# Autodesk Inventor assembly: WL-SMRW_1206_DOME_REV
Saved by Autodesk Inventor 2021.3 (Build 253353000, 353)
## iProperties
Created: 2023-03
Part Number: WL-SMRW_1206_DOME_REV
Document SubType Name: Assembly
Designer: AdminForWorker
Title: WL-SMRW_1206_DOME_REV
Author: AdminForWorker
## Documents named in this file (7)
- z:\worker\convert-fusion-r08-cosv3\tmp\job-1\3553\output\files\82b4d9ad-b575-4129-b9ca-4964d6b72adf\WL-SMRW_1206_DOME_REV.iam
- z:\worker\convert-fusion-r08-cosv3\tmp\job-1\3553\output\files\82b4d9ad-b575-4129-b9ca-4964d6b72adf\Base.ipt
- z:\worker\convert-fusion-r08-cosv3\tmp\job-1\3553\output\files\82b4d9ad-b575-4129-b9ca-4964d6b72adf\Contacts.ipt
- z:\worker\convert-fusion-r08-cosv3\tmp\job-1\3553\output\files\82b4d9ad-b575-4129-b9ca-4964d6b72adf\Contacts (1).ipt
- z:\worker\convert-fusion-r08-cosv3\tmp\job-1\3553\output\files\82b4d9ad-b575-4129-b9ca-4964d6b72adf\Cup.ipt
- z:\worker\convert-fusion-r08-cosv3\tmp\job-1\3553\output\files\82b4d9ad-b575-4129-b9ca-4964d6b72adf\Marking.ipt
- z:\worker\convert-fusion-r08-cosv3\tmp\job-1\3553\output\files\82b4d9ad-b575-4129-b9ca-4964d6b72adf\LED.ipt
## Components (6 placed, 6 different names)
1. Base:1
2. Contacts:1
3. Contacts (1):1
4. Cup:1
5. Marking:1
6. LED:1
